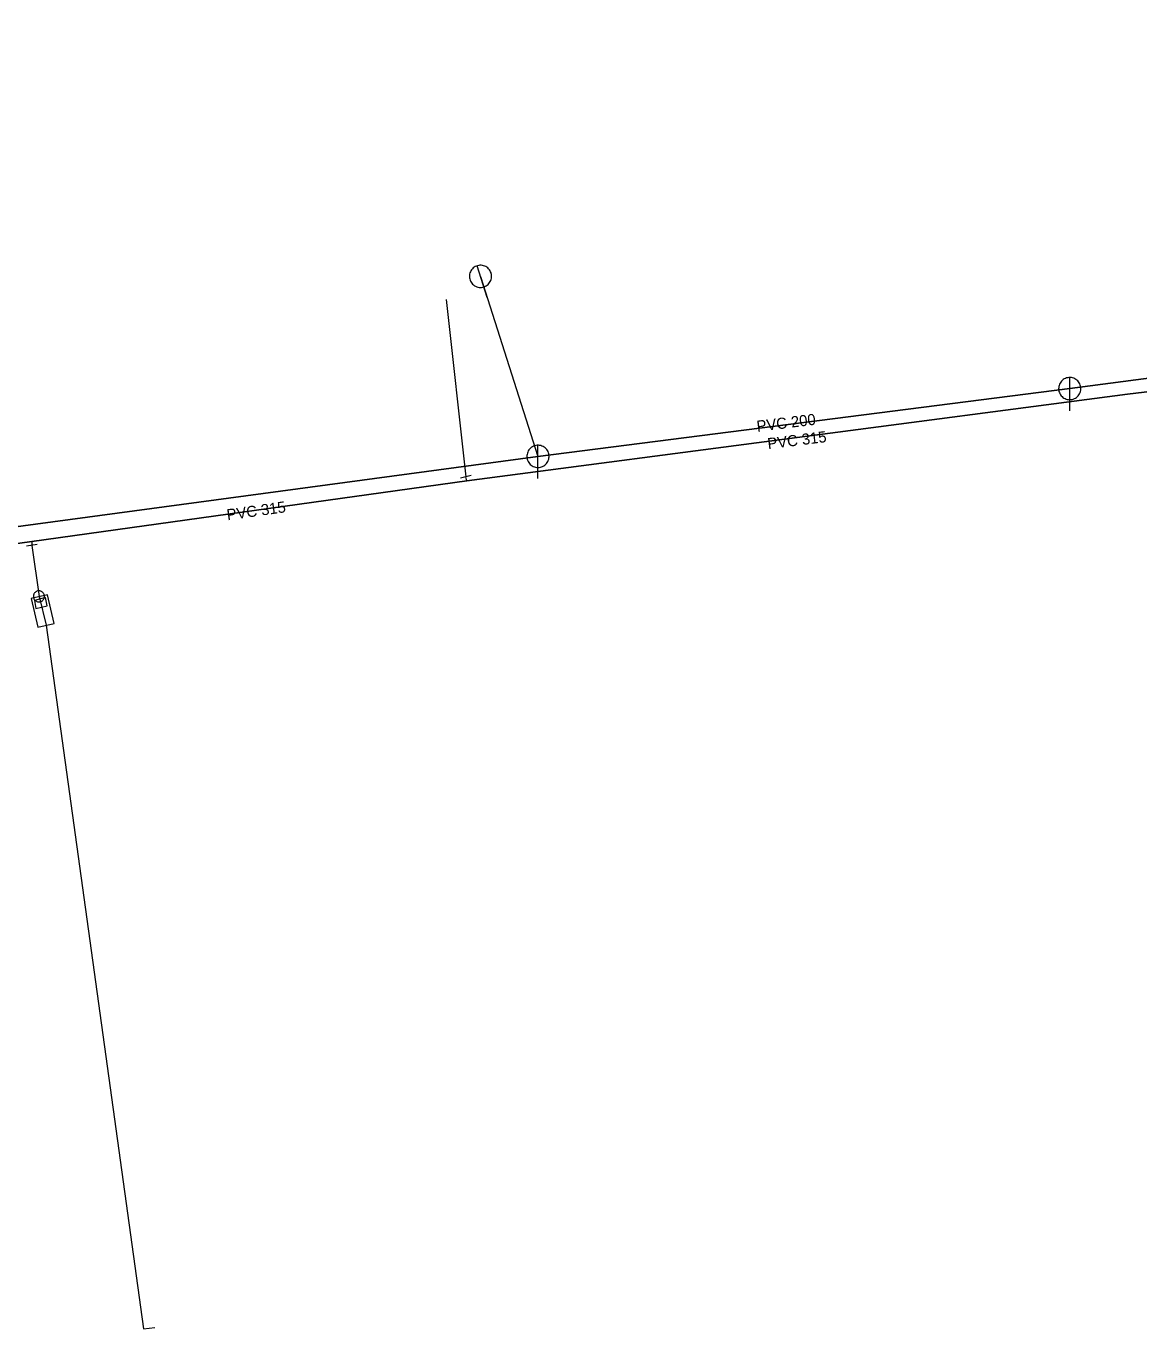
# Model space of a CAD drawing. Extents: x -807203 to -805207, y -993656 to -992505.
# Drawn here: x -807026.3 to -806926, y -993094.6 to -992977.1 of the extents above; entities that cross this region are included whole.
import ezdxf

# ---------------------------------------------------------------- set-up
doc = ezdxf.new("R2010")
doc.units = 0
doc.header["$LTSCALE"] = 0.4
for name, color, linetype, lineweight in [('1', 7, 'Continuous', 13), ('11', 7, 'Continuous', 13), ('13', 7, 'Continuous', 13), ('14', 7, 'Continuous', 25), ('17', 7, 'Continuous', 25), ('2', 7, 'Continuous', 13), ('22', 7, 'Continuous', 13), ('23', 7, 'Continuous', 13), ('34', 7, 'Continuous', 13)]:
    doc.layers.add(name, color=color, linetype=linetype, lineweight=lineweight)

msp = doc.modelspace()

# ---------------------------------------------------------------- linework, layer by layer
at = {"layer": '11'}
msp.add_line((-806985.3, -992999.689), (-806980.12, -993015.92), dxfattribs=at)
at = {"layer": '13'}
for p, q in [((-806988.39, -993001.789), (-806986.619, -993017.779)), ((-806986.53, -993018.14), (-806986.619, -993017.779)), ((-807025.739, -993023.949), (-807025.074, -993028.564))]:
    msp.add_line(p, q, dxfattribs=at)
msp.add_lwpolyline([(-807025.074, -993028.564), (-807024.46, -993031.145), (-807015.673, -993094.6), (-807014.649, -993094.458)], dxfattribs=at)
at = {"layer": '14', "lineweight": 13}
msp.add_line((-807025.75, -993023.6), (-807025.739, -993023.949), dxfattribs=at)
at = {"layer": '14'}
msp.add_lwpolyline([(-807063.899, -993027.32), (-807029.679, -993022.599), (-806980.12, -993015.92), (-806932.19, -993009.809), (-806883.41, -993003.39), (-806833.609, -992997.23), (-806788.059, -992990.989), (-806765.85, -992988.129), (-806739.039, -992984.52), (-806699.85, -992977.12)], dxfattribs=at)
at = {"layer": '17'}
msp.add_lwpolyline([(-807049.977, -993026.962), (-807025.75, -993023.6), (-806986.53, -993018.14), (-806926.969, -993010.32), (-806889.945, -993005.863)], dxfattribs=at)
at = {"layer": '2'}
for points in [[(-807024.34, -993028.399), (-807025.809, -993028.73), (-807025.199, -993031.309), (-807023.719, -993030.98)], [(-807024.52, -993028.66), (-807025.51, -993028.91), (-807025.37, -993029.64), (-807024.35, -993029.41)]]:
    msp.add_lwpolyline(points, close=True, dxfattribs=at)
at = {"layer": '22'}
for p, q in [((-806984.691, -993001.594), (-806985.603, -992998.736)), ((-806932.19, -993011.809), (-806932.189, -993008.809)), ((-806980.12, -993017.92), (-806980.119, -993014.92))]:
    msp.add_line(p, q, dxfattribs=at)
for points in [[(-806984.347, -992999.385), (-806984.386, -992999.283), (-806984.436, -992999.185), (-806984.496, -992999.094), (-806984.565, -992999.01), (-806984.644, -992998.933), (-806984.731, -992998.866), (-806984.824, -992998.809), (-806984.923, -992998.763), (-806985.027, -992998.727), (-806985.133, -992998.703), (-806985.242, -992998.69), (-806985.352, -992998.691), (-806985.461, -992998.702), (-806985.568, -992998.726), (-806985.672, -992998.761), (-806985.771, -992998.808), (-806985.865, -992998.864), (-806985.952, -992998.93), (-806986.03, -992999.007), (-806986.1, -992999.09), (-806986.161, -992999.182), (-806986.211, -992999.279), (-806986.251, -992999.382), (-806986.279, -992999.487), (-806986.295, -992999.595), (-806986.299, -992999.705), (-806986.291, -992999.814), (-806986.272, -992999.922), (-806986.24, -993000.027), (-806986.197, -993000.128), (-806986.145, -993000.223), (-806986.081, -993000.312), (-806986.009, -993000.394), (-806985.927, -993000.468), (-806985.838, -993000.532), (-806985.743, -993000.585), (-806985.642, -993000.629), (-806985.537, -993000.66), (-806985.43, -993000.681), (-806985.32, -993000.689), (-806985.211, -993000.685), (-806985.103, -993000.67), (-806984.996, -993000.642), (-806984.894, -993000.603), (-806984.797, -993000.553), (-806984.706, -993000.494), (-806984.621, -993000.423), (-806984.544, -993000.344), (-806984.477, -993000.258), (-806984.42, -993000.165), (-806984.373, -993000.066), (-806984.338, -992999.963), (-806984.313, -992999.856), (-806984.301, -992999.747), (-806984.301, -992999.638), (-806984.312, -992999.528), (-806984.336, -992999.421)], [(-806931.19, -993009.809), (-806931.195, -993009.7), (-806931.213, -993009.592), (-806931.243, -993009.486), (-806931.283, -993009.385), (-806931.335, -993009.288), (-806931.397, -993009.198), (-806931.469, -993009.115), (-806931.549, -993009.041), (-806931.637, -993008.975), (-806931.731, -993008.92), (-806931.831, -993008.875), (-806931.936, -993008.842), (-806932.043, -993008.82), (-806932.152, -993008.81), (-806932.262, -993008.812), (-806932.37, -993008.826), (-806932.477, -993008.851), (-806932.58, -993008.888), (-806932.678, -993008.937), (-806932.77, -993008.995), (-806932.856, -993009.064), (-806932.933, -993009.141), (-806933.002, -993009.227), (-806933.061, -993009.319), (-806933.109, -993009.417), (-806933.146, -993009.52), (-806933.172, -993009.627), (-806933.186, -993009.735), (-806933.189, -993009.845), (-806933.179, -993009.954), (-806933.158, -993010.061), (-806933.124, -993010.165), (-806933.08, -993010.265), (-806933.025, -993010.36), (-806932.959, -993010.448), (-806932.885, -993010.528), (-806932.802, -993010.6), (-806932.712, -993010.662), (-806932.616, -993010.714), (-806932.514, -993010.755), (-806932.409, -993010.785), (-806932.301, -993010.803), (-806932.191, -993010.809), (-806932.082, -993010.803), (-806931.974, -993010.785), (-806931.869, -993010.756), (-806931.767, -993010.715), (-806931.67, -993010.663), (-806931.58, -993010.601), (-806931.497, -993010.53), (-806931.422, -993010.45), (-806931.357, -993010.362), (-806931.301, -993010.268), (-806931.257, -993010.168), (-806931.223, -993010.064), (-806931.201, -993009.956), (-806931.191, -993009.847)], [(-806979.12, -993015.92), (-806979.125, -993015.811), (-806979.143, -993015.703), (-806979.173, -993015.597), (-806979.213, -993015.496), (-806979.265, -993015.399), (-806979.327, -993015.309), (-806979.399, -993015.226), (-806979.479, -993015.152), (-806979.567, -993015.086), (-806979.661, -993015.031), (-806979.761, -993014.986), (-806979.866, -993014.953), (-806979.973, -993014.931), (-806980.082, -993014.921), (-806980.192, -993014.923), (-806980.3, -993014.937), (-806980.407, -993014.962), (-806980.51, -993014.999), (-806980.608, -993015.048), (-806980.7, -993015.106), (-806980.786, -993015.175), (-806980.863, -993015.252), (-806980.932, -993015.338), (-806980.991, -993015.43), (-806981.039, -993015.528), (-806981.076, -993015.631), (-806981.102, -993015.738), (-806981.116, -993015.846), (-806981.119, -993015.956), (-806981.109, -993016.065), (-806981.088, -993016.172), (-806981.054, -993016.276), (-806981.01, -993016.376), (-806980.955, -993016.471), (-806980.889, -993016.559), (-806980.815, -993016.639), (-806980.732, -993016.711), (-806980.642, -993016.773), (-806980.546, -993016.825), (-806980.444, -993016.866), (-806980.339, -993016.896), (-806980.231, -993016.914), (-806980.121, -993016.92), (-806980.012, -993016.914), (-806979.904, -993016.896), (-806979.799, -993016.867), (-806979.697, -993016.826), (-806979.6, -993016.774), (-806979.51, -993016.712), (-806979.427, -993016.641), (-806979.352, -993016.561), (-806979.287, -993016.473), (-806979.231, -993016.379), (-806979.187, -993016.279), (-806979.153, -993016.175), (-806979.131, -993016.067), (-806979.121, -993015.958)]]:
    msp.add_lwpolyline(points, close=True, dxfattribs=at)
at = {"layer": '23'}
for points in [[(-807024.654, -993028.317), (-807024.678, -993028.273), (-807024.709, -993028.23), (-807024.746, -993028.191), (-807024.784, -993028.156), (-807024.827, -993028.125), (-807024.871, -993028.098), (-807024.919, -993028.077), (-807024.97, -993028.062), (-807025.02, -993028.051), (-807025.072, -993028.045), (-807025.124, -993028.045), (-807025.176, -993028.05), (-807025.227, -993028.06), (-807025.278, -993028.077), (-807025.326, -993028.098), (-807025.371, -993028.123), (-807025.412, -993028.155), (-807025.451, -993028.19), (-807025.487, -993028.228), (-807025.518, -993028.271), (-807025.544, -993028.316), (-807025.566, -993028.363), (-807025.582, -993028.413), (-807025.594, -993028.464), (-807025.598, -993028.517), (-807025.598, -993028.568), (-807025.593, -993028.62), (-807025.582, -993028.671), (-807025.567, -993028.721), (-807025.545, -993028.77), (-807025.519, -993028.815), (-807025.488, -993028.858), (-807025.454, -993028.896), (-807025.414, -993028.931), (-807025.373, -993028.962), (-807025.328, -993028.988), (-807025.279, -993029.01), (-807025.23, -993029.026), (-807025.178, -993029.037)], [(-807025.544, -993028.316), (-807025.566, -993028.363), (-807025.582, -993028.413), (-807025.594, -993028.464), (-807025.598, -993028.517), (-807025.598, -993028.568), (-807025.593, -993028.62), (-807025.582, -993028.671), (-807025.567, -993028.721), (-807025.545, -993028.77), (-807025.519, -993028.815), (-807025.488, -993028.858), (-807025.454, -993028.896), (-807025.414, -993028.931), (-807025.373, -993028.962), (-807025.328, -993028.988), (-807025.279, -993029.01), (-807025.23, -993029.026), (-807025.178, -993029.037), (-807025.126, -993029.042), (-807025.075, -993029.043), (-807025.023, -993029.038), (-807024.971, -993029.028), (-807024.921, -993029.011), (-807024.874, -993028.989), (-807024.828, -993028.964), (-807024.786, -993028.933), (-807024.747, -993028.897), (-807024.712, -993028.859), (-807024.682, -993028.817), (-807024.655, -993028.772), (-807024.634, -993028.724), (-807024.617, -993028.674), (-807024.606, -993028.622), (-807024.6, -993028.571), (-807024.6, -993028.52), (-807024.605, -993028.468), (-807024.617, -993028.415), (-807024.632, -993028.366), (-807024.654, -993028.317)], [(-807025.023, -993029.038), (-807024.971, -993029.028), (-807024.921, -993029.011), (-807024.874, -993028.989), (-807024.828, -993028.964), (-807024.786, -993028.933), (-807024.747, -993028.897), (-807024.712, -993028.859), (-807024.682, -993028.817), (-807024.655, -993028.772), (-807024.634, -993028.724), (-807024.617, -993028.674), (-807024.606, -993028.622), (-807024.6, -993028.571), (-807024.6, -993028.52), (-807024.605, -993028.468), (-807024.617, -993028.415), (-807024.632, -993028.366), (-807024.654, -993028.317), (-807024.678, -993028.273), (-807024.709, -993028.23), (-807024.746, -993028.191), (-807024.784, -993028.156), (-807024.827, -993028.125), (-807024.871, -993028.098), (-807024.919, -993028.077), (-807024.97, -993028.062), (-807025.02, -993028.051), (-807025.072, -993028.045), (-807025.124, -993028.045), (-807025.176, -993028.05), (-807025.227, -993028.06), (-807025.278, -993028.077), (-807025.326, -993028.098), (-807025.371, -993028.123), (-807025.412, -993028.155), (-807025.451, -993028.19), (-807025.487, -993028.228), (-807025.518, -993028.271), (-807025.544, -993028.316)], [(-807025.178, -993029.037), (-807025.126, -993029.042), (-807025.075, -993029.043), (-807025.023, -993029.038)]]:
    msp.add_lwpolyline(points, dxfattribs=at)
at = {"layer": '34'}
for p, q in [((-806986.134, -993017.657), (-806987.104, -993017.899)), ((-807025.244, -993023.877), (-807026.233, -993024.019))]:
    msp.add_line(p, q, dxfattribs=at)

# ---------------------------------------------------------------- texts
at = {"layer": '1'}
for s, rotation, p in [('PVC 200 ', 7, (-806960.348, -993013.708)), ('PVC 315 ', 7, (-806959.375, -993015.276)), ('PVC 315 ', 8, (-807008.102, -993021.694))]:
    msp.add_text(s, height=1, rotation=rotation, dxfattribs=at).set_placement(p)

doc.saveas('drawing.dxf')
